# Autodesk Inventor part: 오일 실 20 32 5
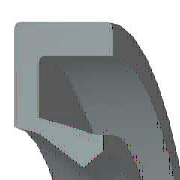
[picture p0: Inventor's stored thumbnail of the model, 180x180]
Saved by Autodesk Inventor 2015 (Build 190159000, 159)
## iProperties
IsCustomPart: 0
Created: 2012-02
Part Number: 오일 실 20 32 5
Material: 고무
Description: 오일 실 - 비스프링, 조립 GA
Document SubType Name: Modeling
Standard: JIS B 2402
Designer: mduedu
Standards Organization: JIS
Language: ko-KR
Size Designation: 20 32 5 A
Categories: <MemberInstance><Categories><Category DisplayName="샤프트 부품" InternalName="7f7aeb1f-a693-4053-b835-cee3144e0d98" Mnemonic="SHFT"><Category DisplayName="실링" Intern
Density: 0.93 g/cm^3
Appearance: Rubber-Black
Author: mduedu
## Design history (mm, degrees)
fillet "모깎기2" dims "d33" = 0.5
body "Solid1"
revolve "회전1" stored, may be unused: angle "d27" = 360 deg
fillet "모깎기1" dims "d28" = 0.25 (= 0.05 x b)
sketch "스케치2"
  geometry: L1 (11.971, -3.75)-(12.571, -5); L2 (11.171, -3.438)-(11.971, -3.75); L3 (10, -1.375)-(11.171, -3.438); L4 (10.923, -0.75)-(10, -1.375); L5 (13.6, -4.375)-(10.923, -0.75); L6 (13.6, -0.25)-(13.6, -4.375); L7 (14.8, -0.25)-(13.6, -0.25); L8 (14.8, 0)-(14.8, -0.25); L9 (16, 0)-(14.8, 0); L10 (16, -5)-(16, 0); L11 (12.571, -5)-(16, -5); L12 (0, -9.6)-(0, 1.6) reference; L13 (28, 0)-(14, 0) reference
  constraints: 22 end point, 3 horizontal, 3 vertical
  dimensions: "d2" = 5 distance of L10.start L9.start (= b); "d4" = 1.2 distance of L9.start L8.start (= 0.1 x dd - 0.1 x Diam); "d6" = 0.25 distance of L8.start L7.start (= 0.05 x b); "d8" = 0.92308 horizontal distance of L4.start L3.start (= 0.0769231 x dd - 0.0769231 x Diam); "d10" = 0.625 vertical distance of L5.start L10.start (= 0.125 x b); "d12" = 1.2 distance of L7.start L6.start (= 0.1 x dd - 0.1 x Diam); "d14" = 0.5 vertical distance of L4.start L6.start (= 0.1 x b); "d16" = 3.42857 distance of L1.end L10.start (= 0.285714 x dd - 0.285714 x Diam); "d18" = 0.6 horizontal distance of L1.start L1.end (= 0.05 x dd - 0.05 x Diam); "d20" = 0.625 vertical distance of L4.start L3.start (= 0.125 x b); "d22" = 1.25 vertical distance of L1.start L1.end (= 0.25 x b); "d24" = 0.8 horizontal distance of L2.start L1.start (= 0.0666667 x dd - 0.0666667 x Diam); "d26" = 0.3125 vertical distance of L2.start L1.start (= 0.0625 x b); "d29" = 0 distance between parallel lines of L13 L9; "d30" = 10 distance from line of L3.start L12 (= 0.5 x Diam); "d31" = 16 distance between parallel lines of L12 L10 (= 0.5 x dd)
other parameters: "dd" = 32 [user parameter; used in 7 equation terms], "b" = 5 [user parameter; used in 8 equation terms], "d1" = 8 (derived), "d3" = 2 (derived), "d5" = 0.4 (derived), "d7" = 1.53846 (derived), "d9" = 1 (derived), "d11" = 2 (derived), "d13" = 0.8 (derived), "d15" = 5.71429 (derived), "d17" = 1 (derived), "d19" = 1 (derived), "d21" = 2 (derived), "d23" = 1.33333 (derived), "d25" = 0.5 (derived), "d32" = 0
